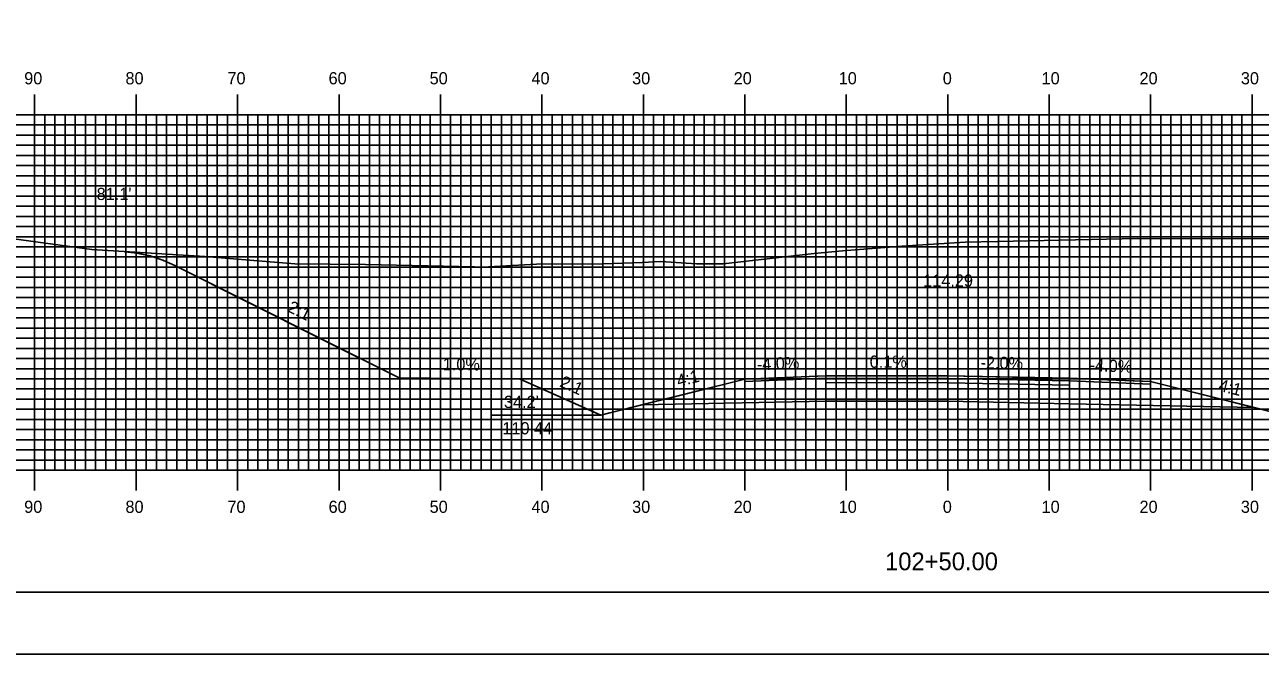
# Model space of a CAD drawing. Extents: x 1767300 to 1767643, y 442591 to 442811.
# Drawn here: x 1767375 to 1767496.7, y 442590.5 to 442652.5 of the extents above; entities that cross this region are included whole.
import ezdxf

# ---------------------------------------------------------------- set-up
doc = ezdxf.new("R2010")
doc.units = 0
for name, color, linetype in [('ANNOTATION', 7, 'Continuous'), ('BORDER', 7, 'Continuous'), ('D_Roadway_Centerline', 7, 'Continuous'), ('D_Roadway_Centerline_Text', 7, 'Continuous'), ('D_Roadway_Edge_Shoulder', 7, 'Continuous'), ('D_Roadway_Edge_TW', 7, 'Continuous'), ('D_Roadway_Pavement', 7, 'Continuous'), ('D_Roadway_SlopeLines', 7, 'Continuous'), ('D_Roadway_SubGrade', 7, 'Continuous'), ('D_Text_Standard', 7, 'Continuous'), ('H_V ANNOTATION', 7, 'Continuous'), ('MAJOR', 7, 'Continuous'), ('MINOR', 7, 'Continuous'), ('PDRAIN', 7, 'Continuous'), ('PLOT BOUNDARY', 7, 'Continuous'), ('S_Roadway_Centerline', 7, 'Continuous')]:
    doc.layers.add(name, color=color, linetype=linetype)

msp = doc.modelspace()

# ---------------------------------------------------------------- linework, layer by layer
at = {"layer": 'BORDER'}
msp.add_lwpolyline([(1767316.34, 442596.67), (1767636.34, 442596.67), (1767636.34, 442806.67), (1767316.34, 442806.67)], close=True, dxfattribs=at)
at = {"layer": 'D_Roadway_Centerline'}
msp.add_lwpolyline([(1767384.81, 442630.19), (1767385.55, 442630.11), (1767386.06, 442630.05), (1767386.32, 442629.99), (1767387.31, 442629.77), (1767388.56, 442629.35), (1767389.81, 442628.79), (1767404.15, 442621.62), (1767411.86, 442617.77), (1767411.87, 442617.77), (1767423.79, 442617.65), (1767427.92, 442615.81), (1767431.76, 442614.1), (1767432.63, 442614.32), (1767435.76, 442615.1), (1767435.76, 442615.1), (1767438.87, 442615.88), (1767445.94, 442617.65), (1767445.94, 442617.65), (1767453.07, 442617.93), (1767453.94, 442617.97), (1767465.93, 442617.96), (1767465.94, 442617.96), (1767477.01, 442617.73), (1767477.94, 442617.72), (1767478.31, 442617.7), (1767485.93, 442617.4), (1767485.94, 442617.4), (1767493.5, 442615.51), (1767496.11, 442614.85), (1767498.75, 442614.19)], dxfattribs=at)
at = {"layer": 'D_Roadway_Edge_Shoulder'}
for points in [[(1767453.94, 442617.97), (1767445.94, 442617.65), (1767445.94, 442617.4), (1767453.94, 442617.72)], [(1767477.94, 442617.72), (1767485.94, 442617.4), (1767485.94, 442617.15), (1767477.94, 442617.47)]]:
    msp.add_lwpolyline(points, close=True, dxfattribs=at)
at = {"layer": 'D_Roadway_Edge_TW'}
msp.add_lwpolyline([(1767453.94, 442617.72), (1767453.94, 442617.97), (1767465.94, 442617.96), (1767477.94, 442617.72), (1767477.94, 442617.47), (1767465.94, 442617.71)], close=True, dxfattribs=at)
at = {"layer": 'D_Roadway_Pavement'}
msp.add_lwpolyline([(1767453.94, 442617.3), (1767453.94, 442617.72), (1767465.94, 442617.71), (1767477.94, 442617.47), (1767477.94, 442617.05), (1767465.94, 442617.29)], close=True, dxfattribs=at)
at = {"layer": 'D_Roadway_SlopeLines'}
for points in [[(1767423.79, 442617.65), (1767411.86, 442617.77), (1767389.81, 442628.79), (1767388.56, 442629.35), (1767387.31, 442629.77), (1767386.06, 442630.05), (1767384.81, 442630.19)], [(1767431.76, 442614.1), (1767423.79, 442617.65)], [(1767445.94, 442617.65), (1767431.76, 442614.1)], [(1767485.94, 442617.4), (1767500.11, 442613.85)]]:
    msp.add_lwpolyline(points, dxfattribs=at)
at = {"layer": 'D_Roadway_SubGrade'}
msp.add_lwpolyline([(1767453.94, 442615.47), (1767435.76, 442615.1), (1767445.94, 442617.65), (1767445.94, 442617.4), (1767453.94, 442617.72), (1767465.94, 442617.71), (1767477.94, 442617.47), (1767485.94, 442617.15), (1767485.94, 442617.4), (1767496.11, 442614.85), (1767477.94, 442615.22), (1767465.94, 442615.46)], close=True, dxfattribs=at)
at = {"layer": 'MAJOR'}
for p, q in [((1767375.94, 442645.67), (1767375.94, 442643.67)), ((1767385.94, 442645.67), (1767385.94, 442643.67)), ((1767395.94, 442645.67), (1767395.94, 442643.67)), ((1767405.94, 442645.67), (1767405.94, 442643.67)), ((1767415.94, 442645.67), (1767415.94, 442643.67)), ((1767425.94, 442645.67), (1767425.94, 442643.67)), ((1767435.94, 442645.67), (1767435.94, 442643.67)), ((1767445.94, 442645.67), (1767445.94, 442643.67)), ((1767455.94, 442645.67), (1767455.94, 442643.67)), ((1767465.94, 442645.67), (1767465.94, 442643.67)), ((1767475.94, 442645.67), (1767475.94, 442643.67)), ((1767485.94, 442645.67), (1767485.94, 442643.67)), ((1767495.94, 442645.67), (1767495.94, 442643.67)), ((1767325.94, 442643.67), (1767605.94, 442643.67)), ((1767325.94, 442643.67), (1767605.94, 442643.67)), ((1767375.94, 442608.67), (1767375.94, 442643.67)), ((1767385.94, 442608.67), (1767385.94, 442643.67)), ((1767395.94, 442608.67), (1767395.94, 442643.67)), ((1767405.94, 442608.67), (1767405.94, 442643.67)), ((1767415.94, 442608.67), (1767415.94, 442643.67)), ((1767425.94, 442608.67), (1767425.94, 442643.67)), ((1767435.94, 442608.67), (1767435.94, 442643.67)), ((1767445.94, 442608.67), (1767445.94, 442643.67)), ((1767455.94, 442608.67), (1767455.94, 442643.67)), ((1767465.94, 442608.67), (1767465.94, 442643.67)), ((1767475.94, 442608.67), (1767475.94, 442643.67)), ((1767485.94, 442608.67), (1767485.94, 442643.67)), ((1767495.94, 442608.67), (1767495.94, 442643.67)), ((1767325.94, 442638.67), (1767605.94, 442638.67)), ((1767325.94, 442633.67), (1767605.94, 442633.67)), ((1767325.94, 442628.67), (1767605.94, 442628.67)), ((1767325.94, 442623.67), (1767605.94, 442623.67)), ((1767325.94, 442618.67), (1767605.94, 442618.67)), ((1767325.94, 442613.67), (1767605.94, 442613.67)), ((1767325.94, 442608.67), (1767605.94, 442608.67)), ((1767325.94, 442608.67), (1767605.94, 442608.67)), ((1767375.94, 442606.66), (1767375.94, 442608.67)), ((1767385.94, 442606.66), (1767385.94, 442608.67)), ((1767395.94, 442606.66), (1767395.94, 442608.67)), ((1767405.94, 442606.66), (1767405.94, 442608.67)), ((1767415.94, 442606.66), (1767415.94, 442608.67)), ((1767425.94, 442606.66), (1767425.94, 442608.67)), ((1767435.94, 442606.66), (1767435.94, 442608.67)), ((1767445.94, 442606.66), (1767445.94, 442608.67)), ((1767455.94, 442606.66), (1767455.94, 442608.67)), ((1767465.94, 442606.66), (1767465.94, 442608.67)), ((1767475.94, 442606.66), (1767475.94, 442608.67)), ((1767485.94, 442606.66), (1767485.94, 442608.67)), ((1767495.94, 442606.66), (1767495.94, 442608.67))]:
    msp.add_line(p, q, dxfattribs=at)
at = {"layer": 'MINOR'}
for p, q in [((1767376.94, 442608.67), (1767376.94, 442643.67)), ((1767377.94, 442608.67), (1767377.94, 442643.67)), ((1767378.94, 442608.67), (1767378.94, 442643.67)), ((1767379.94, 442608.67), (1767379.94, 442643.67)), ((1767380.94, 442608.67), (1767380.94, 442643.67)), ((1767381.94, 442608.67), (1767381.94, 442643.67)), ((1767382.94, 442608.67), (1767382.94, 442643.67)), ((1767383.94, 442608.67), (1767383.94, 442643.67)), ((1767384.94, 442608.67), (1767384.94, 442643.67)), ((1767386.94, 442608.67), (1767386.94, 442643.67)), ((1767387.94, 442608.67), (1767387.94, 442643.67)), ((1767388.94, 442608.67), (1767388.94, 442643.67)), ((1767389.94, 442608.67), (1767389.94, 442643.67)), ((1767390.94, 442608.67), (1767390.94, 442643.67)), ((1767391.94, 442608.67), (1767391.94, 442643.67)), ((1767392.94, 442608.67), (1767392.94, 442643.67)), ((1767393.94, 442608.67), (1767393.94, 442643.67)), ((1767394.94, 442608.67), (1767394.94, 442643.67)), ((1767396.94, 442608.67), (1767396.94, 442643.67)), ((1767397.94, 442608.67), (1767397.94, 442643.67)), ((1767398.94, 442608.67), (1767398.94, 442643.67)), ((1767399.94, 442608.67), (1767399.94, 442643.67)), ((1767400.94, 442608.67), (1767400.94, 442643.67)), ((1767401.94, 442608.67), (1767401.94, 442643.67)), ((1767402.94, 442608.67), (1767402.94, 442643.67)), ((1767403.94, 442608.67), (1767403.94, 442643.67)), ((1767404.94, 442608.67), (1767404.94, 442643.67)), ((1767406.94, 442608.67), (1767406.94, 442643.67)), ((1767407.94, 442608.67), (1767407.94, 442643.67)), ((1767408.94, 442608.67), (1767408.94, 442643.67)), ((1767409.94, 442608.67), (1767409.94, 442643.67)), ((1767410.94, 442608.67), (1767410.94, 442643.67)), ((1767411.94, 442608.67), (1767411.94, 442643.67)), ((1767412.94, 442608.67), (1767412.94, 442643.67)), ((1767413.94, 442608.67), (1767413.94, 442643.67)), ((1767414.94, 442608.67), (1767414.94, 442643.67)), ((1767416.94, 442608.67), (1767416.94, 442643.67)), ((1767417.94, 442608.67), (1767417.94, 442643.67)), ((1767418.94, 442608.67), (1767418.94, 442643.67)), ((1767419.94, 442608.67), (1767419.94, 442643.67)), ((1767420.94, 442608.67), (1767420.94, 442643.67)), ((1767421.94, 442608.67), (1767421.94, 442643.67)), ((1767422.94, 442608.67), (1767422.94, 442643.67)), ((1767423.94, 442608.67), (1767423.94, 442643.67)), ((1767424.94, 442608.67), (1767424.94, 442643.67)), ((1767426.94, 442608.67), (1767426.94, 442643.67)), ((1767427.94, 442608.67), (1767427.94, 442643.67)), ((1767428.94, 442608.67), (1767428.94, 442643.67)), ((1767429.94, 442608.67), (1767429.94, 442643.67)), ((1767430.94, 442608.67), (1767430.94, 442643.67)), ((1767431.94, 442608.67), (1767431.94, 442643.67)), ((1767432.94, 442608.67), (1767432.94, 442643.67)), ((1767433.94, 442608.67), (1767433.94, 442643.67)), ((1767434.94, 442608.67), (1767434.94, 442643.67)), ((1767436.94, 442608.67), (1767436.94, 442643.67)), ((1767437.94, 442608.67), (1767437.94, 442643.67)), ((1767438.94, 442608.67), (1767438.94, 442643.67)), ((1767439.94, 442608.67), (1767439.94, 442643.67)), ((1767440.94, 442608.67), (1767440.94, 442643.67)), ((1767441.94, 442608.67), (1767441.94, 442643.67)), ((1767442.94, 442608.67), (1767442.94, 442643.67)), ((1767443.94, 442608.67), (1767443.94, 442643.67)), ((1767444.94, 442608.67), (1767444.94, 442643.67)), ((1767446.94, 442608.67), (1767446.94, 442643.67)), ((1767447.94, 442608.67), (1767447.94, 442643.67)), ((1767448.94, 442608.67), (1767448.94, 442643.67)), ((1767449.94, 442608.67), (1767449.94, 442643.67)), ((1767450.94, 442608.67), (1767450.94, 442643.67)), ((1767451.94, 442608.67), (1767451.94, 442643.67)), ((1767452.94, 442608.67), (1767452.94, 442643.67)), ((1767453.94, 442608.67), (1767453.94, 442643.67)), ((1767454.94, 442608.67), (1767454.94, 442643.67)), ((1767456.94, 442608.67), (1767456.94, 442643.67)), ((1767457.94, 442608.67), (1767457.94, 442643.67)), ((1767458.94, 442608.67), (1767458.94, 442643.67)), ((1767459.94, 442608.67), (1767459.94, 442643.67)), ((1767460.94, 442608.67), (1767460.94, 442643.67)), ((1767461.94, 442608.67), (1767461.94, 442643.67)), ((1767462.94, 442608.67), (1767462.94, 442643.67)), ((1767463.94, 442608.67), (1767463.94, 442643.67)), ((1767464.94, 442608.67), (1767464.94, 442643.67)), ((1767466.94, 442608.67), (1767466.94, 442643.67)), ((1767467.94, 442608.67), (1767467.94, 442643.67)), ((1767468.94, 442608.67), (1767468.94, 442643.67)), ((1767469.94, 442608.67), (1767469.94, 442643.67)), ((1767470.94, 442608.67), (1767470.94, 442643.67)), ((1767471.94, 442608.67), (1767471.94, 442643.67)), ((1767472.94, 442608.67), (1767472.94, 442643.67)), ((1767473.94, 442608.67), (1767473.94, 442643.67)), ((1767474.94, 442608.67), (1767474.94, 442643.67)), ((1767476.94, 442608.67), (1767476.94, 442643.67)), ((1767477.94, 442608.67), (1767477.94, 442643.67)), ((1767478.94, 442608.67), (1767478.94, 442643.67)), ((1767479.94, 442608.67), (1767479.94, 442643.67)), ((1767480.94, 442608.67), (1767480.94, 442643.67)), ((1767481.94, 442608.67), (1767481.94, 442643.67)), ((1767482.94, 442608.67), (1767482.94, 442643.67)), ((1767483.94, 442608.67), (1767483.94, 442643.67)), ((1767484.94, 442608.67), (1767484.94, 442643.67)), ((1767486.94, 442608.67), (1767486.94, 442643.67)), ((1767487.94, 442608.67), (1767487.94, 442643.67)), ((1767488.94, 442608.67), (1767488.94, 442643.67)), ((1767489.94, 442608.67), (1767489.94, 442643.67)), ((1767490.94, 442608.67), (1767490.94, 442643.67)), ((1767491.94, 442608.67), (1767491.94, 442643.67)), ((1767492.94, 442608.67), (1767492.94, 442643.67)), ((1767493.94, 442608.67), (1767493.94, 442643.67)), ((1767494.94, 442608.67), (1767494.94, 442643.67)), ((1767325.94, 442642.67), (1767605.94, 442642.67)), ((1767325.94, 442641.67), (1767605.94, 442641.67)), ((1767325.94, 442640.67), (1767605.94, 442640.67)), ((1767325.94, 442639.67), (1767605.94, 442639.67)), ((1767325.94, 442637.67), (1767605.94, 442637.67)), ((1767325.94, 442636.67), (1767605.94, 442636.67)), ((1767325.94, 442635.67), (1767605.94, 442635.67)), ((1767325.94, 442634.67), (1767605.94, 442634.67)), ((1767325.94, 442632.67), (1767605.94, 442632.67)), ((1767325.94, 442631.67), (1767605.94, 442631.67)), ((1767325.94, 442630.67), (1767605.94, 442630.67)), ((1767325.94, 442629.67), (1767605.94, 442629.67)), ((1767325.94, 442627.67), (1767605.94, 442627.67)), ((1767325.94, 442626.67), (1767605.94, 442626.67)), ((1767325.94, 442625.67), (1767605.94, 442625.67)), ((1767325.94, 442624.67), (1767605.94, 442624.67)), ((1767325.94, 442622.67), (1767605.94, 442622.67)), ((1767325.94, 442621.67), (1767605.94, 442621.67)), ((1767325.94, 442620.67), (1767605.94, 442620.67)), ((1767325.94, 442619.67), (1767605.94, 442619.67)), ((1767325.94, 442617.67), (1767605.94, 442617.67)), ((1767325.94, 442616.67), (1767605.94, 442616.67)), ((1767325.94, 442615.67), (1767605.94, 442615.67)), ((1767325.94, 442614.67), (1767605.94, 442614.67)), ((1767325.94, 442612.67), (1767605.94, 442612.67)), ((1767325.94, 442611.67), (1767605.94, 442611.67)), ((1767325.94, 442610.67), (1767605.94, 442610.67)), ((1767325.94, 442609.67), (1767605.94, 442609.67))]:
    msp.add_line(p, q, dxfattribs=at)
at = {"layer": 'PDRAIN'}
msp.add_line((1767421.04, 442614.1), (1767431.76, 442614.1), dxfattribs=at)
at = {"layer": 'PLOT BOUNDARY'}
msp.add_lwpolyline([(1767300.15, 442590.55), (1767640.15, 442590.55), (1767640.15, 442810.55), (1767300.15, 442810.55)], close=True, dxfattribs=at)
at = {"layer": 'S_Roadway_Centerline'}
msp.add_lwpolyline([(1767373.18, 442631.54), (1767381.58, 442630.39), (1767392.72, 442629.72), (1767401.6, 442629), (1767408.54, 442628.92), (1767419.29, 442628.69), (1767420.07, 442628.68), (1767426.01, 442629.01), (1767427.4, 442628.96), (1767431.89, 442628.98), (1767435.82, 442629.13), (1767437.66, 442629.22), (1767441.17, 442629.01), (1767443.81, 442628.99), (1767452.78, 442630.01), (1767455.58, 442630.28), (1767461.43, 442630.73), (1767467.65, 442631.14), (1767470.86, 442631.19), (1767484.67, 442631.49), (1767502.67, 442631.45)], dxfattribs=at)

# ---------------------------------------------------------------- texts
at = {"layer": 'ANNOTATION'}
for s, rotation, p in [('2:1', 333.4363, (1767400.77, 442624.35)), ('1.0%', 359.4283, (1767416.16, 442618.52)), ('-4.0%', 2.2908, (1767447.14, 442618.5)), ('0.1%', 359.9427, (1767458.25, 442618.76)), ('-2.0%', 358.8543, (1767469.16, 442618.69)), ('-4.0%', 357.7092, (1767479.91, 442618.44)), ('2:1', 336.0358, (1767427.61, 442616.94)), ('4:1', 14.0384, (1767439.39, 442616.87)), ('4:1', 345.9622, (1767492.57, 442616.51))]:
    msp.add_text(s, height=1.2, rotation=rotation, dxfattribs=at).set_placement(p)
for s, p in [("34.2'", (1767422.2, 442614.8)), ('110.44', (1767422.04, 442612.2))]:
    msp.add_text(s, height=1.2, dxfattribs=at).set_placement(p)
at = {"layer": 'D_Roadway_Centerline'}
for s, p in [('C', (1767465.93, 442617.96)), ('L', (1767465.94, 442617.95))]:
    msp.add_text(s, height=0.0146, dxfattribs=at).set_placement(p)
at = {"layer": 'D_Roadway_Centerline_Text'}
msp.add_text('114.29', height=1.2, dxfattribs=at).set_placement((1767463.52, 442626.75))
at = {"layer": 'D_Text_Standard'}
msp.add_text("81.1'", height=1.2, dxfattribs=at).set_placement((1767382.05, 442635.28))
at = {"layer": 'H_V ANNOTATION'}
for s, height, p in [('90', 1.2, (1767374.91, 442646.67)), ('80', 1.2, (1767384.89, 442646.67)), ('70', 1.2, (1767394.94, 442646.67)), ('60', 1.2, (1767404.91, 442646.67)), ('50', 1.2, (1767414.87, 442646.67)), ('40', 1.2, (1767424.91, 442646.67)), ('30', 1.2, (1767434.83, 442646.67)), ('20', 1.2, (1767444.84, 442646.67)), ('10', 1.2, (1767455.19, 442646.67)), ('0', 1.2, (1767465.45, 442646.67)), ('10', 1.2, (1767475.19, 442646.67)), ('20', 1.2, (1767484.84, 442646.67)), ('30', 1.2, (1767494.83, 442646.67)), ('90', 1.2, (1767374.91, 442604.47)), ('80', 1.2, (1767384.89, 442604.47)), ('70', 1.2, (1767394.94, 442604.47)), ('60', 1.2, (1767404.91, 442604.47)), ('50', 1.2, (1767414.87, 442604.47)), ('40', 1.2, (1767424.91, 442604.47)), ('30', 1.2, (1767434.83, 442604.47)), ('20', 1.2, (1767444.84, 442604.47)), ('10', 1.2, (1767455.19, 442604.47)), ('0', 1.2, (1767465.45, 442604.47)), ('10', 1.2, (1767475.19, 442604.47)), ('20', 1.2, (1767484.84, 442604.47)), ('30', 1.2, (1767494.83, 442604.47)), ('102+50.00', 1.75, (1767459.76, 442598.82))]:
    msp.add_text(s, height=height, dxfattribs=at).set_placement(p)

doc.saveas('drawing.dxf')
